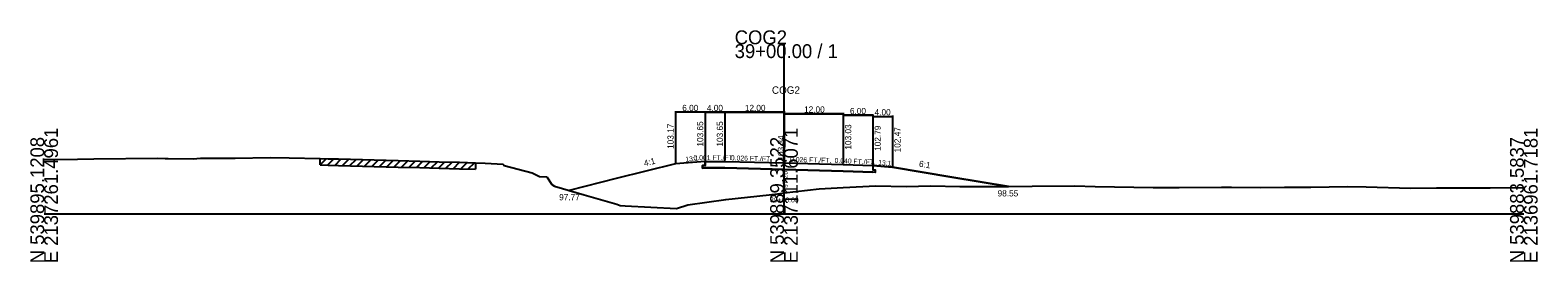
# Model space of a CAD drawing. Extents: x -13397 to 2303, y -10 to 39059.
# Drawn here: x 997.2 to 1302.8, y 17990.3 to 18037.2 of the extents above; entities that cross this region are included whole.
import ezdxf

# ---------------------------------------------------------------- set-up
doc = ezdxf.new("R2010")
doc.units = 0
for name, color, linetype in [('Level 5', 7, 'Continuous'), ('Level 53', 7, 'Continuous'), ('Level 54', 7, 'Continuous'), ('Level 55', 7, 'Continuous'), ('Level 7', 7, 'Continuous'), ('RD_GPK_XS_Cell', 7, 'Continuous'), ('RD_XS_EwShp', 7, 'Continuous'), ('RD_XS_ExGround', 7, 'Continuous'), ('RD_XS_ExPaveRet', 7, 'Continuous'), ('RD_XS_Pave', 7, 'Continuous'), ('RD_XS_TX_Baseline', 7, 'Continuous'), ('RD_XS_TX_Elev_EX', 7, 'Continuous'), ('RD_XS_TX_Elev_PR', 7, 'Continuous'), ('RD_XS_TX_Station', 7, 'Continuous')]:
    doc.layers.add(name, color=color, linetype=linetype)

msp = doc.modelspace()

# ---------------------------------------------------------------- linework, layer by layer
at = {"layer": 'Level 5'}
for p, q in [((1134, 18009.82), (1133.5, 18009.81)), ((1133.5, 18009.81), (1133.5, 18009.31)), ((1133.5, 18009.31), (1134, 18009.32)), ((1134, 18010.65), (1134, 18009.82)), ((1138, 18009.32), (1134, 18009.32)), ((1138, 18009.32), (1134, 18009.32)), ((1138, 18009.32), (1134, 18009.32)), ((1134, 18009.32), (1138, 18009.32)), ((1150, 18009.01), (1138, 18009.32)), ((1150, 18009.01), (1138, 18009.32)), ((1150, 18009.01), (1138, 18009.32)), ((1138, 18009.32), (1150, 18009.01)), ((1138, 18009.32), (1150, 18009.01)), ((1162, 18008.69), (1150, 18009.01)), ((1162, 18008.69), (1150, 18009.01)), ((1150, 18009.01), (1162, 18008.69)), ((1150, 18009.01), (1162, 18008.69)), ((1150, 18009.01), (1162, 18008.69)), ((1168, 18008.45), (1162, 18008.69)), ((1162, 18008.69), (1168, 18008.45)), ((1162, 18008.69), (1168, 18008.45)), ((1162, 18008.69), (1168, 18008.45)), ((1168, 18009.79), (1168, 18008.95)), ((1168, 18008.95), (1168.5, 18008.93)), ((1168.5, 18008.43), (1168, 18008.45)), ((1168.5, 18008.93), (1168.5, 18008.43))]:
    msp.add_line(p, q, dxfattribs=at)
at = {"layer": 'Level 54'}
for p, q in [((1128, 18020.8), (1128, 18010.37)), ((1134, 18020.6), (1128, 18020.6)), ((1134, 18020.8), (1134, 18010.85)), ((1134, 18020.8), (1134, 18010.85)), ((1134, 18020.8), (1134, 18010.85)), ((1134, 18020.8), (1134, 18010.85)), ((1134, 18020.8), (1134, 18010.85)), ((1134, 18020.6), (1138, 18020.6)), ((1134, 18020.6), (1138, 18020.6)), ((1134, 18020.6), (1138, 18020.6)), ((1138, 18020.6), (1134, 18020.6)), ((1138, 18020.8), (1138, 18010.85)), ((1138, 18020.8), (1138, 18010.85)), ((1138, 18020.8), (1138, 18010.85)), ((1138, 18020.8), (1138, 18010.85)), ((1138, 18020.8), (1138, 18010.85)), ((1138, 18020.8), (1138, 18010.85)), ((1138, 18020.8), (1138, 18010.85)), ((1138, 18020.8), (1138, 18010.85)), ((1138, 18020.8), (1138, 18010.85)), ((1138, 18020.6), (1150, 18020.6)), ((1138, 18020.6), (1150, 18020.6)), ((1138, 18020.6), (1150, 18020.6)), ((1150, 18020.6), (1138, 18020.6)), ((1150, 18020.6), (1138, 18020.6)), ((1150, 18020.8), (1150, 18010.54)), ((1150, 18020.8), (1150, 18010.54)), ((1150, 18020.8), (1150, 18010.54)), ((1150, 18020.8), (1150, 18010.54)), ((1150, 18020.8), (1150, 18010.54)), ((1150, 18020.49), (1150, 18010.54)), ((1150, 18020.49), (1150, 18010.54)), ((1150, 18020.49), (1150, 18010.54)), ((1150, 18020.49), (1150, 18010.54)), ((1150, 18020.49), (1150, 18010.54)), ((1150, 18020.29), (1162, 18020.29)), ((1150, 18020.29), (1162, 18020.29)), ((1162, 18020.29), (1150, 18020.29)), ((1162, 18020.29), (1150, 18020.29)), ((1162, 18020.29), (1150, 18020.29)), ((1162, 18020.49), (1162, 18010.23)), ((1162, 18020.49), (1162, 18010.23)), ((1162, 18020.49), (1162, 18010.23)), ((1162, 18020.49), (1162, 18010.23)), ((1162, 18020.49), (1162, 18010.23)), ((1162, 18020.18), (1162, 18010.23)), ((1162, 18020.18), (1162, 18010.23)), ((1162, 18020.18), (1162, 18010.23)), ((1162, 18020.18), (1162, 18010.23)), ((1162, 18019.98), (1168, 18019.98)), ((1168, 18019.98), (1162, 18019.98)), ((1168, 18019.98), (1162, 18019.98)), ((1168, 18019.98), (1162, 18019.98)), ((1168, 18020.18), (1168, 18009.99)), ((1168, 18020.18), (1168, 18009.99)), ((1168, 18020.18), (1168, 18009.99)), ((1168, 18020.18), (1168, 18009.99)), ((1168, 18019.94), (1168, 18009.99)), ((1172, 18019.94), (1172, 18009.67)), ((1168, 18019.74), (1172, 18019.74))]:
    msp.add_line(p, q, dxfattribs=at)
at = {"layer": 'Level 7'}
for p, q in [((1128, 18010.17), (1116, 18007.17)), ((1134, 18010.65), (1128, 18010.17)), ((1168, 18009.79), (1172, 18009.47)), ((1172, 18009.47), (1184, 18007.47)), ((1116, 18007.17), (1106.41, 18004.77)), ((1184, 18007.47), (1195.5, 18005.55))]:
    msp.add_line(p, q, dxfattribs=at)
at = {"layer": 'RD_GPK_XS_Cell'}
for p, q in [((1150, 18000), (1150, 18034.38)), ((1000, 18000), (1150, 18000)), ((1150, 18000), (1300, 18000))]:
    msp.add_line(p, q, dxfattribs=at)
at = {"layer": 'RD_XS_EwShp'}
msp.add_lwpolyline([(1179.74, 18005.71), (1185.67, 18005.54), (1193.61, 18005.53), (1195.5, 18005.55), (1184, 18007.47), (1172, 18009.47), (1168, 18009.79), (1168, 18008.95), (1168.5, 18008.93), (1168.5, 18008.43), (1168, 18008.45), (1162, 18008.69), (1150, 18009.01), (1138, 18009.32), (1134, 18009.32), (1133.5, 18009.31), (1133.5, 18009.81), (1134, 18009.82), (1134, 18010.65), (1128, 18010.17), (1116, 18007.17), (1106.41, 18004.77), (1109.48, 18003.87), (1116.12, 18002), (1116.78, 18001.7), (1117.79, 18001.62), (1128.17, 18001.12), (1130.52, 18001.88), (1138.19, 18002.91), (1146.98, 18003.87), (1149.21, 18004.17), (1150, 18004.26), (1157.11, 18005.07), (1161.99, 18005.38), (1168.62, 18005.73), (1174.77, 18005.57)], close=True, dxfattribs=at)
at = {"layer": 'RD_XS_ExGround'}
for p, q in [((1000, 18011.03), (1006.79, 18011.13)), ((1006.79, 18011.13), (1010.04, 18011.2)), ((1010.04, 18011.2), (1022.99, 18011.27)), ((1022.99, 18011.27), (1024.55, 18011.26)), ((1024.55, 18011.26), (1025.11, 18011.26)), ((1025.11, 18011.26), (1030.21, 18011.18)), ((1030.21, 18011.18), (1031.69, 18011.32)), ((1031.69, 18011.32), (1038.75, 18011.3)), ((1038.75, 18011.3), (1045.82, 18011.46)), ((1045.82, 18011.46), (1049.67, 18011.35)), ((1049.67, 18011.35), (1055.97, 18011.25)), ((1055.97, 18011.25), (1057.57, 18011.2)), ((1057.57, 18011.2), (1059.67, 18011.15)), ((1059.67, 18011.15), (1071.76, 18010.81)), ((1071.76, 18010.81), (1076.16, 18010.69)), ((1076.16, 18010.69), (1080.06, 18010.58)), ((1080.06, 18010.58), (1084.22, 18010.47)), ((1084.22, 18010.47), (1087.46, 18010.36)), ((1087.46, 18010.36), (1089.38, 18010.29)), ((1089.38, 18010.29), (1093.04, 18010.08)), ((1093.04, 18010.08), (1093.26, 18009.81)), ((1093.26, 18009.81), (1098.93, 18008.33)), ((1098.93, 18008.33), (1100.46, 18007.6)), ((1100.46, 18007.6), (1101.92, 18007.51)), ((1101.92, 18007.51), (1102.91, 18005.99)), ((1102.91, 18005.99), (1103.47, 18005.63)), ((1103.47, 18005.63), (1109.48, 18003.87)), ((1150, 18004.26), (1157.11, 18005.07)), ((1157.11, 18005.07), (1161.99, 18005.38)), ((1161.99, 18005.38), (1168.62, 18005.73)), ((1168.62, 18005.73), (1174.77, 18005.57)), ((1174.77, 18005.57), (1179.74, 18005.71)), ((1179.74, 18005.71), (1185.67, 18005.54)), ((1185.67, 18005.54), (1193.61, 18005.53)), ((1193.61, 18005.53), (1200.34, 18005.61)), ((1200.34, 18005.61), (1208.99, 18005.69)), ((1208.99, 18005.69), (1213.12, 18005.58)), ((1213.12, 18005.58), (1224.88, 18005.33)), ((1224.88, 18005.33), (1225.47, 18005.33)), ((1225.47, 18005.33), (1225.91, 18005.33)), ((1225.91, 18005.33), (1230.1, 18005.37)), ((1230.1, 18005.37), (1238.69, 18005.42)), ((1238.69, 18005.42), (1240.71, 18005.43)), ((1240.71, 18005.43), (1246.66, 18005.36)), ((1246.66, 18005.36), (1251.47, 18005.43)), ((1251.47, 18005.43), (1256.79, 18005.43)), ((1256.79, 18005.43), (1264.25, 18005.53)), ((1264.25, 18005.53), (1268.04, 18005.51)), ((1268.04, 18005.51), (1277.04, 18005.23)), ((1277.04, 18005.23), (1282.3, 18005.3)), ((1282.3, 18005.3), (1288.94, 18005.27)), ((1288.94, 18005.27), (1289.82, 18005.26)), ((1289.82, 18005.26), (1293.2, 18005.3)), ((1293.2, 18005.3), (1300, 18005.36)), ((1109.48, 18003.87), (1116.12, 18002)), ((1116.12, 18002), (1116.78, 18001.7)), ((1116.78, 18001.7), (1117.79, 18001.62)), ((1117.79, 18001.62), (1128.17, 18001.12)), ((1128.17, 18001.12), (1130.52, 18001.88)), ((1130.52, 18001.88), (1138.19, 18002.91)), ((1138.19, 18002.91), (1146.98, 18003.87)), ((1146.98, 18003.87), (1149.21, 18004.17)), ((1149.21, 18004.17), (1150, 18004.26))]:
    msp.add_line(p, q, dxfattribs=at)
at = {"layer": 'RD_XS_ExPaveRet'}
for p, q in [((1055.97, 18009.95), (1055.97, 18011.25)), ((1055.97, 18009.95), (1057.23, 18011.21)), ((1057.47, 18009.91), (1058.74, 18011.18)), ((1058.97, 18009.87), (1060.24, 18011.14)), ((1060.47, 18009.83), (1061.74, 18011.1)), ((1061.97, 18009.79), (1063.24, 18011.05)), ((1063.47, 18009.75), (1064.74, 18011.01)), ((1064.97, 18009.7), (1066.24, 18010.97)), ((1066.47, 18009.66), (1067.74, 18010.92)), ((1067.97, 18009.62), (1069.24, 18010.88)), ((1069.47, 18009.57), (1070.74, 18010.84)), ((1070.97, 18009.53), (1072.24, 18010.8)), ((1072.47, 18009.49), (1073.74, 18010.76)), ((1055.97, 18009.95), (1057.57, 18009.9)), ((1057.57, 18009.9), (1059.67, 18009.85)), ((1059.67, 18009.85), (1071.76, 18009.51)), ((1071.76, 18009.51), (1076.16, 18009.39)), ((1073.97, 18009.45), (1075.24, 18010.71)), ((1075.47, 18009.41), (1076.74, 18010.67)), ((1076.16, 18009.39), (1080.06, 18009.28)), ((1076.97, 18009.37), (1078.24, 18010.63)), ((1078.47, 18009.33), (1079.74, 18010.59)), ((1079.97, 18009.29), (1081.24, 18010.55)), ((1080.06, 18009.28), (1084.22, 18009.17)), ((1081.47, 18009.25), (1082.74, 18010.51)), ((1082.97, 18009.21), (1084.24, 18010.47)), ((1084.22, 18009.17), (1087.46, 18009.06)), ((1084.47, 18009.16), (1085.73, 18010.42)), ((1085.97, 18009.11), (1087.23, 18010.37)), ((1087.46, 18010.36), (1087.46, 18009.06))]:
    msp.add_line(p, q, dxfattribs=at)
at = {"layer": 'RD_XS_Pave'}
for p, q in [((1134, 18010.65), (1138, 18010.65)), ((1138, 18010.65), (1150, 18010.34)), ((1150, 18010.34), (1162, 18010.03)), ((1162, 18010.03), (1168, 18009.79))]:
    msp.add_line(p, q, dxfattribs=at)

# ---------------------------------------------------------------- texts
at = {"layer": 'Level 53'}
for s, rotation, p in [('103.17', 90, (1127.62, 18013.17)), ('103.65', 90, (1133.62, 18013.65)), ('103.65', 90, (1137.62, 18013.65)), ('103.65', 90, (1137.62, 18013.65)), ('103.65', 90, (1137.62, 18013.65)), ('103.03', 90, (1163.63, 18013.03)), ('103.03', 90, (1163.63, 18013.03)), ('103.03', 90, (1163.63, 18013.03)), ('102.79', 90, (1169.62, 18012.79)), ('102.47', 90, (1173.62, 18012.47)), ('4:1', 14.0362, (1121.76, 18009.64)), ('6:1', 350.5377, (1177.3, 18009.6))]:
    msp.add_text(s, height=1.25, rotation=rotation, dxfattribs=at).set_placement(p)
for s, p in [('98.55', (1193.31, 18003.55)), ('97.77', (1104.41, 18002.77))]:
    msp.add_text(s, height=1.25, dxfattribs=at).set_placement(p)
at = {"layer": 'Level 54'}
for s, p in [('6.00', (1129.37, 18020.85)), ('4.00', (1134.37, 18020.85)), ('4.00', (1134.37, 18020.85)), ('4.00', (1134.37, 18020.85)), ('4.00', (1134.37, 18020.85)), ('12.00', (1142.07, 18020.85)), ('12.00', (1142.07, 18020.85)), ('12.00', (1142.07, 18020.85)), ('12.00', (1142.07, 18020.85)), ('12.00', (1142.07, 18020.85)), ('12.00', (1154.07, 18020.54)), ('12.00', (1154.07, 18020.54)), ('12.00', (1154.07, 18020.54)), ('12.00', (1154.07, 18020.54)), ('12.00', (1154.07, 18020.54)), ('6.00', (1163.37, 18020.23)), ('6.00', (1163.37, 18020.23)), ('6.00', (1163.37, 18020.23)), ('6.00', (1163.37, 18020.23)), ('4.00', (1168.37, 18019.99))]:
    msp.add_text(s, height=1.25, dxfattribs=at).set_placement(p)
at = {"layer": 'Level 55'}
for s, rotation, p in [('13:1', 4.5739, (1130.03, 18010.58)), ('0.001 FT./FT.', 0.0537, (1131.65, 18010.9)), ('0.001 FT./FT.', 0.0537, (1131.65, 18010.9)), ('0.001 FT./FT.', 0.0537, (1131.65, 18010.9)), ('0.001 FT./FT.', 0.0537, (1131.65, 18010.9)), ('0.026 FT./FT.', 358.5083, (1139.22, 18010.87)), ('0.026 FT./FT.', 358.5083, (1139.22, 18010.87)), ('0.026 FT./FT.', 358.5083, (1139.22, 18010.87)), ('0.026 FT./FT.', 358.5083, (1139.22, 18010.87)), ('0.026 FT./FT.', 358.5083, (1139.22, 18010.87)), ('0.026 FT./FT.', 358.5083, (1151.22, 18010.56)), ('0.026 FT./FT.', 358.5083, (1151.22, 18010.56)), ('0.026 FT./FT.', 358.5083, (1151.22, 18010.56)), ('0.026 FT./FT.', 358.5083, (1151.22, 18010.56)), ('0.026 FT./FT.', 358.5083, (1151.22, 18010.56)), ('0.040 FT./FT.', 357.7094, (1160.24, 18010.35)), ('0.040 FT./FT.', 357.7094, (1160.24, 18010.35)), ('0.040 FT./FT.', 357.7094, (1160.24, 18010.35)), ('0.040 FT./FT.', 357.7094, (1160.24, 18010.35)), ('13:1', 355.4261, (1169.07, 18009.95))]:
    msp.add_text(s, height=1, rotation=rotation, dxfattribs=at).set_placement(p)
at = {"layer": 'RD_GPK_XS_Cell'}
for s, p in [('COG2', (1140, 18034.38)), ('39+00.00 / 1', (1140, 18031.58))]:
    msp.add_text(s, height=2.8, dxfattribs=at).set_placement(p)
for s, p in [('E 2137261.4961', (1002.8, 17990)), ('E 2137111.6071', (1152.8, 17990)), ('E 2136961.7181', (1302.8, 17990)), ('N 539895.1208', (1000, 17990)), ('N 539889.3522', (1150, 17990)), ('N 539883.5837', (1300, 17990))]:
    msp.add_text(s, height=2.8, rotation=90, dxfattribs=at).set_placement(p)
at = {"layer": 'RD_XS_TX_Baseline'}
msp.add_text('COG2', height=1.5, dxfattribs=at).set_placement((1147.55, 18024.34))
at = {"layer": 'RD_XS_TX_Elev_EX'}
msp.add_text('97.26', height=1, rotation=90, dxfattribs=at).set_placement((1150.75, 18005.26))
at = {"layer": 'RD_XS_TX_Elev_PR'}
msp.add_text(' 103.34', height=1.25, rotation=90, dxfattribs=at).set_placement((1150, 18010.34))
at = {"layer": 'RD_XS_TX_Station'}
msp.add_text('39+00.00', height=1, dxfattribs=at).set_placement((1147.17, 18002.34))

doc.saveas('drawing.dxf')
